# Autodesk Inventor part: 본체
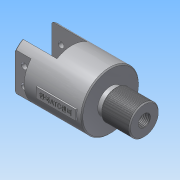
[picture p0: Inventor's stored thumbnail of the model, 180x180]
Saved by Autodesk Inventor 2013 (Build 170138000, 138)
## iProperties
Created: 2019-02
Part Number: 본체
Material: 알루미늄 6061
Document SubType Name: Modeling
Designer: Administrator
Density: 2.71 g/cm^3
Mass: 351.529 g
Surface Area: 290.316 cm^2
Volume: 129.716 cm^3
Author: Administrator
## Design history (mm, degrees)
sketch "스케치1"
  geometry: C1 r 29 at (0, 0); 1 further point
  constraints: 1 centre point, 1 coincident
  dimensions: "d0" = 58 diameter of C1
extrude "돌출1" new body sketch "스케치1" distance "d1" = 74; taper "d2" = 0 deg
sketch "스케치2"
  geometry: L1 (-22, 18.894)-(-22, -18.894); L2 (22, 18.894)-(22, -18.894); A1 r 29 centre (0, 0) between (-22, 18.894) and (-22, -18.894) reference
  constraints: 4 end point, 4 point on circle, 1 horizontal alignment, 1 vertical
  dimensions: "d3" = 44 distance between parallel lines of L2 L1
extrude "돌출2" cut sketch "스케치2" distance "d4" = 16; taper "d5" = 0 deg
sketch "스케치3"
  geometry: L1 (22, -18.894)-(22, 18.894) reference; L2 (-15, 24.819)-(-15, -24.819); L3 (15, -24.819)-(15, 24.819); A1 r 29 centre (0, 0) between (-22, -18.894) and (22, -18.894) reference; A2 r 29 centre (0, 0) between (22, 18.894) and (-22, 18.894) reference
  constraints: 4 end point, 4 point on circle, 2 parallel, 1 horizontal alignment
  dimensions: "d6" = 30 distance between parallel lines of L3 L2
extrude "돌출3" cut sketch "스케치3" distance "d7" = 35; taper "d8" = 0 deg
sketch "스케치4"
  geometry: L1 (-29, 39)-(29, 39) reference; L2 (29, 39)-(29, 0) reference; L3 (29, 0)-(-29, 0) reference; L4 (-29, 0)-(-29, 39) reference; L5 (0, 0)-(0, -34); L6 (0, -34)-(15, -34); L7 (15, -34)-(15, -5); L8 (15, -5)-(13, -5); L9 (13, -5)-(13, 0)
  constraints: 10 end point, 3 parallel, 2 perpendicular, 1 point on line
  dimensions: "d9" = 34 distance of L5.start L5.end; "d10" = 5 distance between parallel lines of L8 L3; "d11" = 26 diameter of L9 L5; "d12" = 30 diameter of L7 L5
revolve "회전1" sketch "스케치4" stored, may be unused: angle "d13" = 90 deg
sketch "스케치5"
  geometry: L1 (0, 0)-(0, 37.789) reference; L2 (16, 0)-(16, 37.789) reference; L3 (16, 18.894)-(0, 18.894); C1 r 3 at (9, 9.894); C2 r 3 at (9, 27.894); 1 further point
  constraints: 2 centre point, 2 end point, 2 midpoint, 1 vertical alignment
  dimensions: "d14" = 6 diameter of C1; "d15" = 6 diameter of C2; "d16" = 9 distance from line of C1.centre L1; "d17" = 18 distance of C2.centre C1.centre; "d18" = 9 distance from line of L3 C2.centre
extrude "돌출4" cut sketch "스케치5" stored distance "d19" = 35; taper "d20" = 0 deg
sketch "스케치6"
  geometry: L1 (-29, 39)-(29, 39) reference; L2 (29, 39)-(29, 0) reference; L3 (29, 0)-(13, 0) reference; L4 (13, 0)-(13, -5) reference; L5 (13, -5)-(15, -5) reference; L6 (15, -5)-(15, -34) reference; L7 (15, -34)-(-15, -34) reference; L8 (-15, -34)-(-15, -5) reference; L9 (-15, -5)-(-13, -5) reference; L10 (-13, -5)-(-13, 0) reference; L11 (-13, 0)-(-29, 0) reference; L12 (-29, 0)-(-29, 39) reference; L13 (0, 39)-(0, -34); L14 (14, 39)-(14, 36.35); L15 (14, 36.35)-(17, 36.35); L16 (17, 36.35)-(17, 31.65); L17 (17, 31.65)-(14, 31.65); L18 (14, 31.65)-(14, 27.35); L19 (14, 27.35)-(17, 27.35); L20 (17, 27.35)-(17, 22.65); L21 (17, 22.65)-(14, 22.65); L22 (14, 22.65)-(14, 19); L23 (14, 19)-(16, 19); L24 (16, 19)-(16, 12); L25 (16, 12)-(4, 12); L26 (4, 12)-(4, -12); L27 (4, -12)-(7, -12); L28 (7, -12)-(7, -34); L29 (7, -34)-(0, -34); L30 (17, 34)-(0, 34); L31 (17, 25)-(0, 25); 1 further point
  constraints: 38 end point, 10 parallel, 8 perpendicular, 4 midpoint, 4 point on line
  dimensions: "d21" = 28 diameter of L14 L13; "d23" = 34 diameter of L16 L13; "d24" = 28 diameter of L18 L13; "d26" = 34 diameter of L20 L13; "d27" = 28 diameter of L22 L13; "d28" = 32 diameter of L24 L13; "d29" = 4.7 distance of L15.end L16.end; "d30" = 4.7 distance of L19.end L20.end; "d31" = 7 distance of L23.end L24.end; "d32" = 8 diameter of L26 L13; "d33" = 14 diameter of L28 L13; "d34" = 22 distance of L27.end L28.end; "d35" = 27 distance between parallel lines of L25 L1; "d36" = 5 distance from line of L30.start L1; "d37" = 9 distance of L31.start L30.start
revolve "회전2" sketch "스케치6" stored, may be unused: angle "d38" = 90 deg
chamfer "모따기1" distance "d39" = 1; stored, may be unused: second distance "d40" = 2, angle "d41" = 45 deg
chamfer "모따기2" distance "d42" = 1; stored, may be unused: second distance "d43" = 2, angle "d44" = 45 deg
sketch "스케치7"
  geometry: C1 r 7 at (0, 0) reference
extrude "돌출5" join sketch "스케치7" distance "d45" = 22; taper "d46" = 0 deg
sketch "스케치8"
  geometry: C1 r 14 at (0, 0) reference; 1 further point
  constraints: 1 coincident
hole "구멍1" sketch "스케치8" at (0, 0) diameter "d47" = 12.376; stored, may be unused: countersink angle "d51" = 90 deg, drill point angle "d53" = 118 deg; dims "d48" = 18, "d49" = 4, "d50" = 2, "d52" = 22
fillet "모깎기1" dims "d54" = 0.8
feature "스레드1" dims "d55" = 10, "d56" = 0
node "작업 평면1"
sketch "스케치9"
  geometry: L1 (5, 45)-(-5, 45); L2 (-5, 45)-(-5, 5); L3 (-5, 5)-(5, 5); L4 (5, 5)-(5, 45); L5 (14, -34)-(-14, -34) reference; L6 (28, 0)-(-28, 0) reference; 3 further points
  constraints: 8 end point, 2 midpoint, 2 parallel, 1 horizontal, 1 perpendicular, 1 vertical alignment
  dimensions: "d58" = 10 distance of L2.end L3.end; "d60" = 40 distance of L3.end L1.start; "d61" = 5 distance between parallel lines of L6 L3
extrude "돌출6" join sketch "스케치9" stored distance "d62" = 22; taper "d63" = 0 deg
node "작업 평면2"
sketch "스케치10"
  geometry: L1 (5, 5)-(5, 45) reference; L2 (5, 45)-(-5, 45) reference; L3 (-5, 45)-(-5, 5) reference; L4 (-5, 5)-(5, 5) reference; 2 further points
  constraints: 1 other
  dimensions: "d65" = 20 distance from line of L2 point (0, 25); "d66" = 5 distance from line of L3 point (0, 25)
feature "엠보싱1" sketch "스케치10" dims "d67" = 0.5, "d68" = 0
node "솔리드1"
node "절단 모서리 투영1"
node "절단 모서리 투영2"
other parameters: "d64" = 43.5
